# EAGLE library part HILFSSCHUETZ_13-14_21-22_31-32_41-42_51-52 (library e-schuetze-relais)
Hilfsschütz mit 1 Schließer, 4 Öffnern
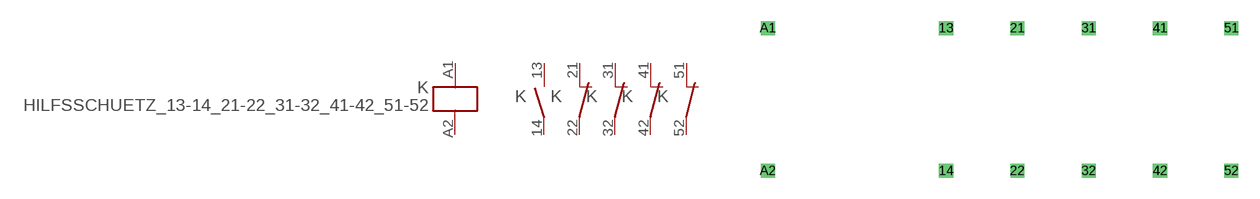
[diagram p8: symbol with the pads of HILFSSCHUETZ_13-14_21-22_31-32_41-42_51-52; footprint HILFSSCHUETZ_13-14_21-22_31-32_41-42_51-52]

Designator prefix K; gates G$1=SPULE 1=SCHLIESSER 2=OEFFNER 3=OEFFNER 4=OEFFNER 5=OEFFNER

## HILFSSCHUETZ_13-14_21-22_31-32_41-42_51-52  [HILFSSCHUETZ_13-14_21-22_31-32_41-42_51-52]
13  1:3  pas
14  1:4  pas
21  2:1  pas
22  2:2  pas
31  3:1  pas
32  3:2  pas
41  4:1  pas
42  4:2  pas
51  5:1  pas
52  5:2  pas
A1  G$1:A1  in
A2  G$1:A2  in

## Footprint HILFSSCHUETZ_13-14_21-22_31-32_41-42_51-52 (pad centres in mm)
Dummy
drill 0.5 pad 1 square: 13 2.54,5.08; 14 2.54,-5.08; 21 7.62,5.08; 22 7.62,-5.08; 31 12.7,5.08; 32 12.7,-5.08; 41 17.78,5.08; 42 17.78,-5.08; 51 22.86,5.08; 52 22.86,-5.08; A1 -10.16,5.08; A2 -10.16,-5.08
